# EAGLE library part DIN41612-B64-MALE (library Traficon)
Manufacturer: Pancon Product number: 100-064-033
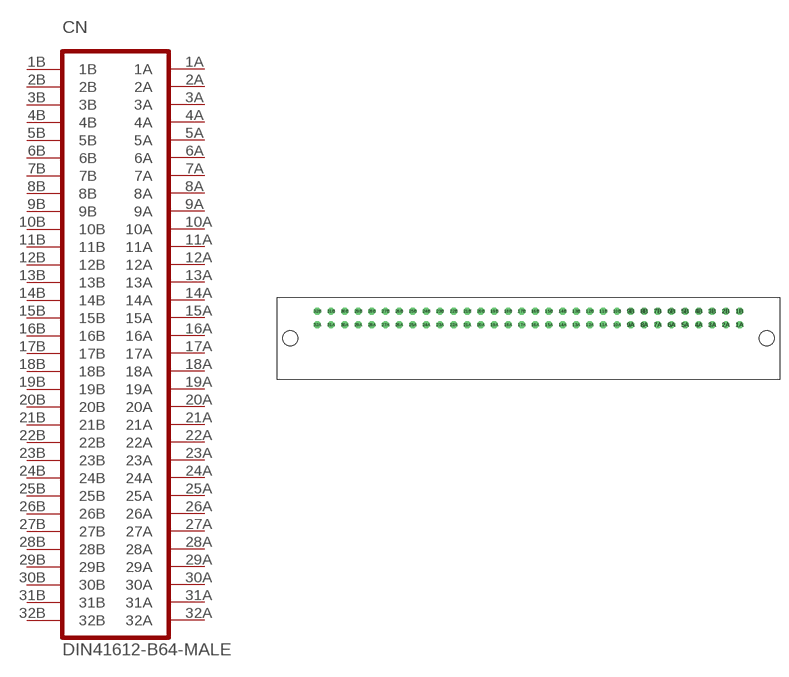
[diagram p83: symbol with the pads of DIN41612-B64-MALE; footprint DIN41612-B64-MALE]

Designator prefix CN

## DIN41612-B64-MALE  [DIN41612-B64-MALE]
1A  1A
1B  1B
2A  2A
2B  2B
3A  3A
3B  3B
4A  4A
4B  4B
5A  5A
5B  5B
6A  6A
6B  6B
7A  7A
7B  7B
8A  8A
8B  8B
9A  9A
9B  9B
10A  10A
10B  10B
11A  11A
11B  11B
12A  12A
12B  12B
13A  13A
13B  13B
14A  14A
14B  14B
15A  15A
15B  15B
16A  16A
16B  16B
17A  17A
17B  17B
18A  18A
18B  18B
19A  19A
19B  19B
20A  20A
20B  20B
21A  21A
21B  21B
22A  22A
22B  22B
23A  23A
23B  23B
24A  24A
24B  24B
25A  25A
25B  25B
26A  26A
26B  26B
27A  27A
27B  27B
28A  28A
28B  28B
29A  29A
29B  29B
30A  30A
30B  30B
31A  31A
31B  31B
32A  32A
32B  32B

## Footprint DIN41612-B64-MALE (pad centres in mm)
drill 0.8 octagon: 1A 58.42,2.54; 1B 58.42,5.08; 2A 55.88,2.54; 2B 55.88,5.08; 3A 53.34,2.54; 3B 53.34,5.08; 4A 50.8,2.54; 4B 50.8,5.08; 5A 48.26,2.54; 5B 48.26,5.08; 6A 45.72,2.54; 6B 45.72,5.08; 7A 43.18,2.54; 7B 43.18,5.08; 8A 40.64,2.54; 8B 40.64,5.08; 9A 38.1,2.54; 9B 38.1,5.08; 10A 35.56,2.54; 10B 35.56,5.08; 11A 33.02,2.54; 11B 33.02,5.08; 12A 30.48,2.54; 12B 30.48,5.08; 13A 27.94,2.54; 13B 27.94,5.08; 14A 25.4,2.54; 14B 25.4,5.08; 15A 22.86,2.54; 15B 22.86,5.08; 16A 20.32,2.54; 16B 20.32,5.08; 17A 17.78,2.54; 17B 17.78,5.08; 18A 15.24,2.54; 18B 15.24,5.08; 19A 12.7,2.54; 19B 12.7,5.08; 20A 10.16,2.54; 20B 10.16,5.08; 21A 7.62,2.54; 21B 7.62,5.08; 22A 5.08,2.54; 22B 5.08,5.08; 23A 2.54,2.54; 23B 2.54,5.08; 24A 0,2.54; 24B 0,5.08; 25A -2.54,2.54; 25B -2.54,5.08; 26A -5.08,2.54; 26B -5.08,5.08; 27A -7.62,2.54; 27B -7.62,5.08; 28A -10.16,2.54; 28B -10.16,5.08; 29A -12.7,2.54; 29B -12.7,5.08; 30A -15.24,2.54; 30B -15.24,5.08; 31A -17.78,2.54; 31B -17.78,5.08; 32A -20.32,2.54; 32B -20.32,5.08
hole 2.8 at -25.4,0
hole 2.8 at 63.5,0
